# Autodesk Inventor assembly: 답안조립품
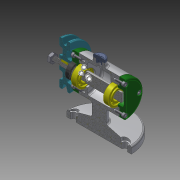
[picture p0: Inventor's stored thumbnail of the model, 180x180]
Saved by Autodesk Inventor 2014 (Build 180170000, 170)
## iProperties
Created: 2018-12
Part Number: 답안조립품
Document SubType Name: Assembly
Designer: oa-51
Author: oa-51
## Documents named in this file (15)
- C:\Users\oa-51\Desktop\481208V1010\481208V1010-시험제출\답안조립품.iam
- C:\Users\oa-51\Desktop\481208V1010\481208V1010-시험제출\본체.ipt
- C:\Users\oa-51\Desktop\481208V1010\V벨트풀리.ipt
- C:\Users\oa-51\Desktop\481208V1010\고무캡.ipt
- C:\Users\oa-51\Desktop\481208V1010\너트 M8.ipt
- 너트 M8.ipt
- C:\Users\oa-51\Desktop\481208V1010\뒤커버.ipt
- C:\Users\oa-51\Desktop\481208V1010\베어링 15 x 32 x 9.ipt
- C:\Users\oa-51\Desktop\481208V1010\볼트 M4 x 12.ipt
- C:\Users\oa-51\Desktop\481208V1010\스프링와셔 8.ipt
- C:\Users\oa-51\Desktop\481208V1010\앞커버.ipt
- C:\Users\oa-51\Desktop\481208V1010\오일 실 15 25 7.ipt
- C:\Users\oa-51\Desktop\481208V1010\와셔 8x17.ipt
- C:\Users\oa-51\Desktop\481208V1010\축.ipt
- C:\Users\oa-51\Desktop\481208V1010\키 3 x 3 x 12.ipt
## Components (2 placed, 2 different names)
1. V벨트풀리:1 — 강체:4, 강체:5
2. 고무캡:1 — 강체:8
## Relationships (3: WeldJoint 3)
- 강체:4 [WeldJoint]: V벨트풀리:1
- 강체:5 [WeldJoint]: V벨트풀리:1
- 강체:8 [WeldJoint]: 고무캡:1
